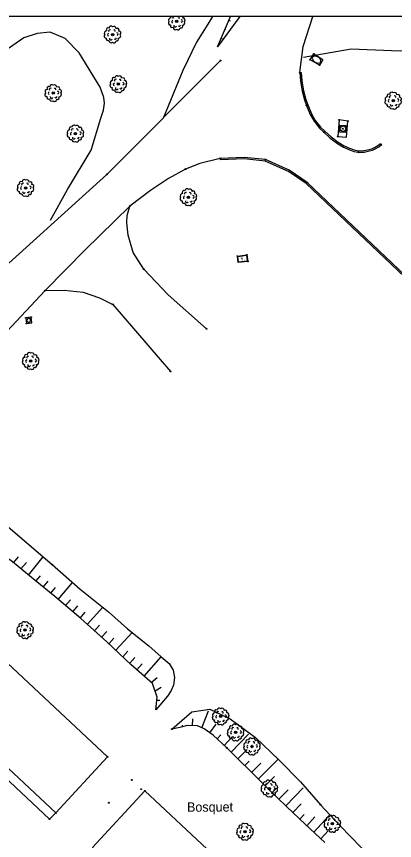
# Model space of a CAD drawing. Extents: x 344013 to 344423, y 298505 to 298795.
# Drawn here: x 344132.3 to 344171.7, y 298706.1 to 298791.9 of the extents above; entities that cross this region are included whole.
import ezdxf

# ---------------------------------------------------------------- set-up
doc = ezdxf.new("R2010")
doc.units = 0
for name, color, linetype in [('Default', 7, 'Continuous'), ('DH_CADRE -CARTOUCHE', 7, 'Continuous'), ('GO MUR EXTERIEUR', 7, 'Continuous'), ('IMM_VOIRIE VOIE FERREE', 7, 'Continuous'), ('PC_CONCRETE', 7, 'Continuous'), ('PS_BOLT', 7, 'Continuous'), ('PS_CONST', 7, 'Continuous'), ('RES_ELECTRICITE', 7, 'Continuous'), ('TOPO_COURBE NIVEAU', 7, 'Continuous'), ('TOPO_POINT', 7, 'Continuous'), ('TOPO_TALUS-TERRAIN NATUREL', 7, 'Continuous'), ('VOIRIE_BORDURE', 7, 'Continuous'), ('VOIRIE_ESPACE VERT', 7, 'Continuous')]:
    doc.layers.add(name, color=color, linetype=linetype)

# ---------------------------------------------------------------- blocks, each defined once
blk = doc.blocks.new('R9')
at = {"layer": 'Default'}
for p, q in [((0, 0), (0, 1)), ((0, 1), (1, 1)), ((1, 0), (0, 0)), ((1, 1), (1, 0))]:
    blk.add_line(p, q, dxfattribs=at)
blk.add_circle((0.5, 0.5), 0.35, dxfattribs=at)
blk = doc.blocks.new('REG_INC')
at = {"layer": 'Default'}
for p, q in [((0, 1), (1, 1)), ((0, 0), (0, 1)), ((1, 1), (1, 0)), ((1, 0), (0, 0))]:
    blk.add_line(p, q, dxfattribs=at)
for centre, start, end in [((0.498, 0.5), 135.00554, 180.00554), ((0.5, 0.498), 90.00577, 135.00577), ((0.5, 0.5), 45.00687, 90.00687), ((0.499, 0.499), 0.00663, 45.00663), ((0.501, 0.5), 180.00663, 225.00663), ((0.499, 0.498), 225.00686, 270.00686), ((0.499, 0.5), 270.00577, 315.00577), ((0.501, 0.499), 315.00554, 0.00554)]:
    blk.add_arc(centre, 0.44, start, end, dxfattribs=at)
blk = doc.blocks.new('RES_ELECTRICITE')
at = {"layer": 'RES_ELECTRICITE'}
for points in [[(0, 0), (0, 1), (1, 1), (1, 0)], [(0.05, 0.05), (0.05, 0.95), (0.95, 0.95), (0.95, 0.05)]]:
    blk.add_lwpolyline(points, close=True, dxfattribs=at)
blk.add_text('EEC', height=0.2, dxfattribs=at).set_placement((0.237, 0.46))
blk = doc.blocks.new('POINT_DISPLAY')
at = {"layer": 'Default'}
blk.add_circle((0, 0), 0.05, dxfattribs=at)
blk = doc.blocks.new('ARB1')
at = {"layer": 'Default'}
blk.add_circle((0, 0), 0.122, dxfattribs=at)
for centre, radius, start, end in [((-0.153, 0.664), 0.211, 43.69255, 183.5969), ((-0.613, 0.139), 0.241, 88.45835, 215.19284), ((-0.471, 0.503), 0.183, 53.95544, 222.20655), ((-0.373, -0.024), 0.149, 103.70924, 242.34652), ((-0.276, 0.37), 0.134, 52.43963, 209.54959), ((0.139, 0.613), 0.241, 358.45835, 125.19284), ((0.164, 0.38), 0.112, 330.58954, 133.71274), ((0.501, 0.468), 0.183, 325.14445, 131.01755), ((0.458, 0.052), 0.137, 276.62143, 88.96702), ((0.613, -0.139), 0.241, 268.45835, 35.19284), ((0.664, 0.153), 0.211, 313.69255, 93.5969), ((-0.664, -0.153), 0.211, 133.69255, 273.5969), ((-0.478, -0.443), 0.19, 155.22426, 300.93774), ((-0.139, -0.613), 0.241, 178.45835, 305.19284), ((-0.163, -0.42), 0.148, 159.53711, 338.16632), ((0.153, -0.664), 0.211, 223.69255, 3.5969), ((0.271, -0.38), 0.112, 210.58954, 13.71274), ((0.448, -0.483), 0.188, 243.13234, 33.02965)]:
    blk.add_arc(centre, radius, start, end, dxfattribs=at)

msp = doc.modelspace()

# ---------------------------------------------------------------- linework, layer by layer
at = {"layer": 'DH_CADRE -CARTOUCHE'}
for points in [[(344012.906, 298504.876), (344422.906, 298504.876), (344422.906, 298791.876), (344012.906, 298791.876)], [(344136.362, 298708.941), (344141.75, 298714.784), (344118.651, 298736.353), (344113.24, 298730.553)], [(344163.929, 298683.13), (344165.092, 298684.375), (344155.123, 298693.692), (344153.96, 298692.447), (344140.184, 298705.334), (344145.624, 298711.233), (344171.024, 298687.508), (344165.544, 298681.621)]]:
    msp.add_lwpolyline(points, close=True, dxfattribs=at)
at = {"layer": 'GO MUR EXTERIEUR'}
for points in [[(344118.651, 298736.353), (344141.75, 298714.784), (344136.362, 298708.941), (344113.24, 298730.553)], [(344145.624, 298711.233), (344171.024, 298687.508), (344165.544, 298681.621), (344140.184, 298705.334)]]:
    msp.add_lwpolyline(points, close=True, dxfattribs=at)
at = {"layer": 'IMM_VOIRIE VOIE FERREE'}
msp.add_lwpolyline([(344161.767, 298786.027), (344162.132, 298788.74), (344163.127, 298791.876)], dxfattribs=at)
at = {"layer": 'PS_BOLT'}
msp.add_lwpolyline([(344166.788, 298780.982), (344165.88, 298781.108), (344165.739, 298779.394), (344166.652, 298779.32)], close=True, dxfattribs=at)
msp.add_lwpolyline([(344136.362, 298708.941), (344135.692, 298708.293), (344122.611, 298720.578), (344112.611, 298729.909), (344113.24, 298730.553)], dxfattribs=at)
at = {"layer": 'TOPO_COURBE NIVEAU'}
for points in [[(344152.676, 298791.876), (344152.194, 298791.069), (344151.014, 298789.21), (344149.601, 298786.256), (344147.576, 298781.35)], [(344162.165, 298787.634), (344167.122, 298788.507), (344171.346, 298788.35), (344172.281, 298788.309), (344173.289, 298788.513), (344175.141, 298789.195), (344175.212, 298789.265), (344176.409, 298790.239), (344176.771, 298790.38), (344177.37, 298790.6)], [(344135.783, 298770.66), (344137.582, 298773.861), (344140.024, 298777.958), (344141.054, 298781.289), (344141.312, 298782.135), (344141.408, 298782.86), (344141.362, 298783.426), (344140.97, 298784.498), (344138.787, 298788.091), (344137.31, 298789.572), (344135.754, 298790.236), (344134.4, 298790.111), (344133.015, 298789.642), (344130.234, 298787.735)]]:
    msp.add_lwpolyline(points, dxfattribs=at)
at = {"layer": 'TOPO_TALUS-TERRAIN NATUREL'}
for p, q in [((344155.538, 298791.876), (344153.194, 298788.716)), ((344153.194, 298788.716), (344154.544, 298791.876)), ((344154.373, 298791.476), (344154.516, 298791.414)), ((344153.98, 298790.556), (344154.041, 298790.53)), ((344153.587, 298789.636), (344153.692, 298789.591)), ((344131.947, 298734.973), (344132.453, 298735.593)), ((344133.496, 298733.707), (344135.044, 298735.6)), ((344132.721, 298734.34), (344133.287, 298735.012)), ((344134.27, 298733.074), (344134.763, 298733.637)), ((344135.047, 298732.444), (344135.551, 298733.066)), ((344136.594, 298731.176), (344138.105, 298732.95)), ((344135.824, 298731.815), (344136.321, 298732.427)), ((344137.356, 298730.527), (344137.875, 298731.136)), ((344138.117, 298729.879), (344138.636, 298730.488)), ((344139.626, 298728.566), (344141.239, 298730.373)), ((344138.879, 298729.23), (344139.398, 298729.839)), ((344140.373, 298727.9), (344140.905, 298728.497)), ((344141.119, 298727.234), (344141.652, 298727.831)), ((344142.594, 298725.882), (344144.308, 298727.725)), ((344141.861, 298726.563), (344142.406, 298727.149)), ((344143.326, 298725.201), (344143.871, 298725.787)), ((344144.059, 298724.52), (344144.603, 298725.106)), ((344145.555, 298723.192), (344147.322, 298725.196)), ((344144.805, 298723.854), (344145.335, 298724.453)), ((344146.305, 298722.53), (344146.899, 298723.041)), ((344146.707, 298721.636), (344147.333, 298722.043)), ((344146.895, 298720.674), (344147.203, 298720.674)), ((344151.553, 298717.815), (344152.266, 298719.564)), ((344150.588, 298718.018), (344150.621, 298718.742)), ((344148.627, 298717.714), (344148.617, 298717.76)), ((344149.602, 298717.935), (344149.566, 298718.078)), ((344152.397, 298717.289), (344153.048, 298718.185)), ((344153.163, 298716.648), (344153.56, 298717.077)), ((344153.896, 298715.968), (344154.734, 298716.873)), ((344154.619, 298715.277), (344156.435, 298717.141)), ((344155.335, 298714.578), (344156.307, 298715.548)), ((344156.041, 298713.87), (344156.503, 298714.33)), ((344156.747, 298713.162), (344157.721, 298714.133)), ((344157.457, 298712.456), (344159.503, 298714.515)), ((344158.166, 298711.751), (344159.138, 298712.729)), ((344158.882, 298711.053), (344159.337, 298711.524)), ((344160.323, 298709.665), (344162.144, 298711.554)), ((344159.603, 298710.359), (344160.561, 298711.354)), ((344161.046, 298708.974), (344161.906, 298709.876)), ((344161.77, 298708.284), (344162.224, 298708.76)), ((344162.497, 298707.597), (344163.342, 298708.516)), ((344163.233, 298706.92), (344164.838, 298708.665)), ((344163.97, 298706.243), (344164.732, 298707.072))]:
    msp.add_line(p, q, dxfattribs=at)
for points in [[(344146.792, 298719.679), (344146.928, 298720.992), (344146.442, 298722.409), (344144.219, 298724.371), (344141.652, 298726.758), (344138.951, 298729.169), (344136.242, 298731.476), (344134.201, 298733.13), (344131.821, 298735.077), (344129.756, 298736.567), (344127.823, 298737.923), (344126.636, 298738.844), (344125.396, 298740.027), (344124.752, 298740.672), (344124.255, 298741.632), (344124.332, 298743.426), (344124.573, 298745.693), (344123.844, 298747.78), (344124.808, 298750.28), (344127.362, 298753.061), (344130.348, 298755.864)], [(344130.348, 298755.864), (344129.139, 298752.757), (344128.047, 298749.375), (344126.893, 298746.388), (344126.71, 298744.759), (344127.026, 298743.068), (344130.916, 298739.136), (344135.968, 298734.808), (344138.904, 298732.255), (344141.857, 298729.875), (344143.823, 298728.108), (344146.055, 298726.342), (344147.327, 298725.192), (344148.161, 298724.497), (344148.568, 298723.821), (344148.724, 298723.034), (344148.613, 298722.231), (344148.361, 298721.682), (344147.974, 298721.092), (344146.792, 298719.679)], [(344148.445, 298717.676), (344150.54, 298719.466), (344152.414, 298719.731), (344154.52, 298718.736), (344157.154, 298716.789), (344159.618, 298714.441), (344161.857, 298712.179), (344163.938, 298709.792), (344165.996, 298707.602), (344168.133, 298705.364), (344169.649, 298703.764), (344171.689, 298701.731), (344173.402, 298700.124), (344174.981, 298698.62), (344176.175, 298697.484), (344177.055, 298696.727), (344177.983, 298696.033), (344178.792, 298695.819), (344179.816, 298696.274), (344181.06, 298697.498), (344181.167, 298697.785)], [(344164.386, 298705.861), (344162.327, 298707.753), (344160.411, 298709.58), (344158.416, 298711.503), (344156.776, 298713.133), (344155.261, 298714.653), (344154.185, 298715.701), (344152.74, 298717.04), (344151.828, 298717.703), (344151.113, 298717.994), (344150.027, 298718.043), (344149.264, 298717.848), (344148.445, 298717.676)]]:
    msp.add_lwpolyline(points, dxfattribs=at)
at = {"layer": 'VOIRIE_BORDURE'}
for points in [[(344012.906, 298718.231), (344022.459, 298709.623), (344035.4, 298697.966), (344038.262, 298695.856), (344041.267, 298693.813), (344044.479, 298691.842), (344047.664, 298690.365), (344050.648, 298689.339), (344052.822, 298689.099), (344054.599, 298689.128), (344056.124, 298689.428), (344057.609, 298690.129), (344058.956, 298690.85), (344060.299, 298691.725), (344061.274, 298692.556), (344063.092, 298694.498), (344091.5, 298724.03), (344099.786, 298732.889), (344115.711, 298749.674), (344123.231, 298757.884), (344127.749, 298762.864), (344141.666, 298775.429), (344153.501, 298787.287)], [(344161.767, 298786.027), (344161.916, 298786.041), (344161.998, 298785.177), (344162.174, 298784.132), (344162.42, 298783.238), (344162.616, 298782.666), (344162.992, 298781.726), (344163.388, 298781.058), (344163.939, 298780.362), (344164.378, 298779.941), (344165.039, 298779.332), (344165.78, 298778.772), (344166.403, 298778.408), (344166.943, 298778.169), (344167.46, 298777.977), (344167.896, 298777.891), (344168.475, 298777.907), (344169, 298778.016), (344169.286, 298778.107), (344169.576, 298778.235), (344169.915, 298778.431), (344170.179, 298778.639), (344170.272, 298778.521)], [(344161.767, 298786.027), (344161.849, 298785.158), (344162.027, 298784.099), (344162.277, 298783.193), (344162.475, 298782.614), (344162.857, 298781.659), (344163.264, 298780.973), (344163.828, 298780.261), (344164.275, 298779.831), (344164.943, 298779.217), (344165.697, 298778.647), (344166.335, 298778.275), (344166.886, 298778.03), (344167.419, 298777.832), (344167.884, 298777.741), (344168.493, 298777.758), (344169.038, 298777.871), (344169.339, 298777.966), (344169.644, 298778.101), (344170, 298778.307), (344170.272, 298778.521)], [(344153.496, 298777.099), (344151.366, 298776.566), (344149.878, 298775.991), (344148.087, 298774.992), (344146.214, 298773.756), (344144.049, 298772.124), (344139.404, 298767.562), (344135.251, 298763.339), (344119.175, 298746.216)], [(344188.08, 298747.552), (344188.298, 298747.793), (344188.542, 298748.122), (344188.677, 298748.455), (344188.76, 298748.789), (344188.686, 298749.153), (344188.576, 298749.491), (344188.431, 298749.766), (344188.222, 298750.046), (344173.457, 298764.241), (344162.536, 298774.583), (344160.66, 298775.87), (344158.196, 298776.968), (344155.978, 298777.192), (344153.496, 298777.099)], [(344188.08, 298747.552), (344187.969, 298747.652), (344188.181, 298747.888), (344188.41, 298748.196), (344188.534, 298748.502), (344188.606, 298748.792), (344188.54, 298749.115), (344188.437, 298749.432), (344188.304, 298749.686), (344188.109, 298749.946), (344173.353, 298764.133), (344162.442, 298774.466), (344160.586, 298775.738), (344158.157, 298776.822), (344155.974, 298777.042), (344153.502, 298776.949), (344153.496, 298777.099)], [(344152.072, 298759.355), (344148.057, 298762.873), (344145.516, 298765.559), (344144.429, 298767.292), (344143.908, 298769.091), (344143.741, 298770.373), (344143.799, 298771.153), (344144.049, 298772.124)], [(344135.251, 298763.339), (344137.236, 298763.36), (344139.21, 298763.15), (344140.911, 298762.573), (344142.296, 298761.887), (344148.316, 298754.908)]]:
    msp.add_lwpolyline(points, dxfattribs=at)
at = {"layer": 'VOIRIE_ESPACE VERT'}
msp.add_circle((344148.952, 298791.354), 0.122, dxfattribs=at)
for centre, radius, start, end in [((344148.288, 298791.201), 0.211, 133.69255, 273.5969), ((344148.339, 298791.493), 0.241, 88.45835, 215.19284), ((344148.481, 298791.857), 0.183, 174.05913, 222.20655), ((344148.579, 298791.33), 0.149, 103.70924, 242.34652), ((344148.675, 298791.724), 0.134, 52.43963, 209.54959), ((344149.115, 298791.733), 0.112, 330.58954, 133.71274), ((344149.409, 298791.406), 0.137, 276.62143, 88.96702), ((344149.564, 298791.215), 0.241, 268.45835, 35.19284), ((344149.452, 298791.822), 0.183, 325.14445, 17.16819), ((344149.616, 298791.506), 0.211, 313.69255, 93.5969), ((344148.474, 298790.911), 0.19, 155.22426, 300.93774), ((344148.813, 298790.741), 0.241, 178.45835, 305.19284), ((344148.789, 298790.934), 0.148, 159.53711, 338.16632), ((344149.104, 298790.69), 0.211, 223.69255, 3.5969), ((344149.223, 298790.974), 0.112, 210.58954, 13.71274), ((344149.4, 298790.871), 0.188, 243.13234, 33.02965)]:
    msp.add_arc(centre, radius, start, end, dxfattribs=at)

# ---------------------------------------------------------------- block references
at = {"layer": 'PC_CONCRETE'}
for name, p, xscale, yscale, rotation in [('REG_INC', (344163.241, 298787.975), 0.700664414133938, 1.1106249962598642, -121.64346), ('REG_INC', (344165.967, 298780.53), 0.6596331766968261, -0.6516362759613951, -3.2854500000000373), ('R9', (344133.3, 298759.911), 0.5862164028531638, -0.544931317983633, 96.96365999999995)]:
    msp.add_blockref(name, p, dxfattribs=dict(at, xscale=xscale, yscale=yscale, rotation=rotation))
at = {"layer": 'RES_ELECTRICITE', "xscale": 0.67844261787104, "yscale": 1.01037054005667, "rotation": 97.36317000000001}
msp.add_blockref('RES_ELECTRICITE', (344156.361, 298766.371), dxfattribs=at)
at = {"layer": 'TOPO_POINT'}
for p in [(344148.952, 298791.354), (344142.261, 298789.995), (344163.241, 298787.975), (344153.501, 298787.287), (344162.874, 298787.378), (344161.767, 298786.027), (344163.831, 298786.815), (344142.865, 298784.833), (344136.081, 298783.9), (344162.475, 298782.614), (344171.512, 298783.112), (344165.88, 298781.108), (344166.788, 298780.982), (344166.279, 298780.187), (344138.395, 298779.682), (344164.275, 298779.831), (344165.739, 298779.394), (344170.272, 298778.521), (344167.884, 298777.741), (344153.496, 298777.099), (344158.196, 298776.968), (344149.878, 298775.991), (344141.666, 298775.429), (344133.197, 298774.022), (344162.536, 298774.583), (344150.17, 298773.054), (344144.049, 298772.124), (344155.273, 298766.913), (344156.274, 298767.044), (344156.361, 298766.371), (344145.516, 298765.559), (344135.251, 298763.339), (344142.296, 298761.887), (344133.229, 298760.493), (344133.77, 298760.56), (344133.3, 298759.911), (344152.072, 298759.355), (344133.73, 298755.999), (344148.316, 298754.908), (344135.968, 298734.808), (344133.154, 298727.972), (344153.533, 298718.982), (344148.445, 298717.676), (344155.091, 298717.315), (344154.185, 298715.701), (344156.788, 298715.855), (344141.75, 298714.784), (344144.263, 298712.373), (344145.245, 298711.412), (344158.614, 298711.475), (344145.624, 298711.233), (344141.888, 298709.992), (344163.938, 298709.792), (344136.362, 298708.941), (344135.692, 298708.293), (344165.178, 298707.803), (344156.067, 298706.978)]:
    msp.add_blockref('POINT_DISPLAY', p, dxfattribs=at)
at = {"layer": 'VOIRIE_ESPACE VERT'}
for p in [(344142.261, 298789.995), (344142.865, 298784.833), (344136.081, 298783.9), (344171.512, 298783.112), (344138.395, 298779.682), (344133.197, 298774.022), (344150.17, 298773.054), (344133.73, 298755.999), (344133.154, 298727.972), (344153.533, 298718.982), (344155.091, 298717.315), (344156.788, 298715.855), (344158.614, 298711.475), (344165.178, 298707.803), (344156.067, 298706.978)]:
    msp.add_blockref('ARB1', p, dxfattribs=at)

# ---------------------------------------------------------------- texts
at = {"layer": 'PS_CONST'}
msp.add_text('Bosquet', height=0.9758, rotation=0.3665, dxfattribs=at).set_placement((344150.031, 298709.055))

doc.saveas('drawing.dxf')
